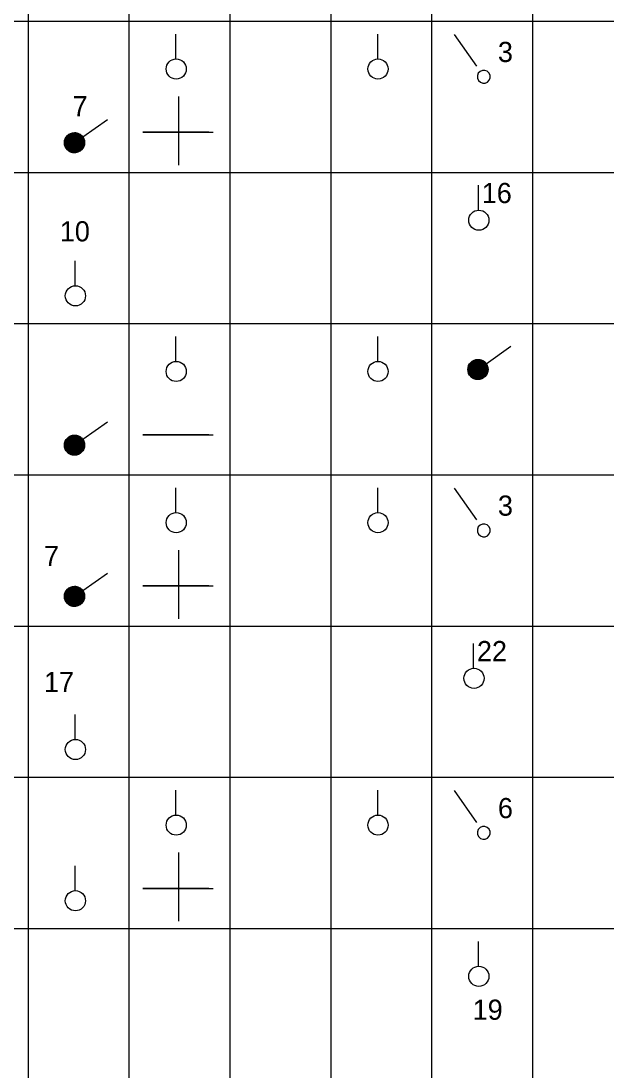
# Model space of a CAD drawing. Extents: x -28 to 822, y 61 to 665.
# Drawn here: x 399.9 to 458, y 142.6 to 246.8 of the extents above; entities that cross this region are included whole.
import ezdxf

# ---------------------------------------------------------------- set-up
doc = ezdxf.new("R2010")
doc.units = 0

# ---------------------------------------------------------------- blocks, each defined once
blk = doc.blocks.new('_X10')
for p, q in [((370.45, 480.11), (371.52, 481.17)), ((370.45, 480.13), (371.5, 481.17)), ((370.45, 480.14), (371.48, 481.17)), ((370.45, 480.16), (371.46, 481.17)), ((370.45, 480.18), (371.45, 481.17)), ((370.45, 480.2), (371.43, 481.17)), ((370.45, 480.21), (371.41, 481.17)), ((370.45, 480.23), (371.39, 481.17)), ((370.46, 480.06), (371.56, 481.17)), ((370.46, 480.08), (371.55, 481.17)), ((370.46, 480.09), (371.53, 481.17)), ((370.46, 480.25), (371.37, 481.17)), ((370.46, 480.27), (371.35, 481.17)), ((370.46, 480.29), (371.33, 481.17)), ((370.46, 480.01), (371.61, 481.16)), ((370.46, 480.03), (371.6, 481.16)), ((370.46, 480.04), (371.58, 481.16)), ((370.46, 480.31), (371.31, 481.16)), ((370.46, 480.33), (371.29, 481.16)), ((370.47, 480), (371.63, 481.16)), ((370.47, 480.35), (371.27, 481.16)), ((370.47, 479.97), (371.66, 481.15)), ((370.47, 479.98), (371.64, 481.15)), ((370.47, 480.37), (371.25, 481.15)), ((370.48, 479.95), (371.67, 481.15)), ((370.48, 480.4), (371.23, 481.15)), ((370.48, 479.93), (371.7, 481.14)), ((370.48, 479.94), (371.68, 481.14)), ((370.48, 480.42), (371.2, 481.14)), ((370.49, 479.91), (371.71, 481.14)), ((370.49, 479.88), (371.74, 481.13)), ((370.49, 479.9), (371.73, 481.13)), ((370.49, 480.45), (371.18, 481.13)), ((370.5, 479.87), (371.75, 481.13)), ((370.5, 480.47), (371.15, 481.13)), ((370.5, 479.86), (371.77, 481.12)), ((370.51, 479.84), (371.78, 481.12)), ((370.51, 480.5), (371.13, 481.12)), ((370.51, 479.83), (371.79, 481.11)), ((370.52, 479.82), (371.81, 481.11)), ((370.52, 480.52), (371.1, 481.11)), ((370.52, 479.81), (371.82, 481.1)), ((370.53, 479.79), (371.83, 481.1)), ((370.53, 480.55), (371.07, 481.1)), ((370.53, 479.78), (371.84, 481.09)), ((370.54, 479.77), (371.86, 481.09)), ((370.54, 479.76), (371.87, 481.08)), ((370.54, 480.58), (371.04, 481.08)), ((370.55, 479.74), (371.88, 481.08)), ((370.55, 479.73), (371.89, 481.07)), ((370.56, 480.62), (371.01, 481.07)), ((370.56, 479.72), (371.9, 481.06)), ((370.57, 479.71), (371.92, 481.06)), ((370.57, 479.7), (371.93, 481.05)), ((370.58, 479.69), (371.94, 481.05)), ((370.58, 480.66), (370.97, 481.05)), ((370.59, 479.67), (371.95, 481.04)), ((370.59, 479.66), (371.96, 481.03)), ((370.6, 479.65), (371.97, 481.03)), ((370.6, 479.64), (371.98, 481.02)), ((370.6, 480.7), (370.93, 481.02)), ((370.61, 479.63), (371.99, 481.01)), ((370.62, 479.62), (372, 481.01)), ((370.63, 479.61), (372.02, 481)), ((370.63, 479.6), (372.03, 480.99)), ((370.64, 480.75), (370.87, 480.99)), ((370.64, 479.59), (372.04, 480.98)), ((370.65, 479.58), (372.05, 480.98)), ((370.66, 479.57), (372.06, 480.97)), ((370.66, 479.56), (372.07, 480.96)), ((370.67, 479.55), (372.08, 480.95)), ((370.68, 479.54), (372.09, 480.95)), ((370.69, 479.53), (372.1, 480.94)), ((370.7, 479.52), (372.11, 480.93)), ((370.7, 479.51), (372.11, 480.92)), ((370.71, 480.84), (370.79, 480.92)), ((370.71, 479.5), (372.12, 480.91)), ((370.72, 479.49), (372.13, 480.9)), ((370.73, 479.48), (372.14, 480.9)), ((370.74, 479.47), (372.15, 480.89)), ((370.75, 479.46), (372.16, 480.88)), ((370.76, 479.46), (372.17, 480.87)), ((370.76, 479.45), (372.18, 480.86)), ((370.77, 479.44), (372.19, 480.85)), ((370.78, 479.43), (372.19, 480.84)), ((370.79, 479.42), (372.2, 480.83)), ((370.8, 479.41), (372.21, 480.82)), ((370.81, 479.4), (372.22, 480.81)), ((370.82, 479.4), (372.23, 480.8)), ((370.83, 479.39), (372.24, 480.79)), ((370.84, 479.38), (372.24, 480.78)), ((370.85, 479.37), (372.25, 480.77)), ((370.86, 479.37), (372.26, 480.76)), ((370.87, 479.36), (372.27, 480.75)), ((370.88, 479.35), (372.27, 480.74)), ((370.89, 479.34), (372.28, 480.73)), ((370.9, 479.34), (372.29, 480.72)), ((370.91, 479.33), (372.29, 480.71)), ((370.92, 479.32), (372.3, 480.7)), ((370.93, 479.32), (372.31, 480.69)), ((370.95, 479.31), (372.31, 480.68)), ((370.96, 479.3), (372.32, 480.67)), ((370.97, 479.3), (372.33, 480.66)), ((370.98, 479.29), (372.33, 480.64)), ((370.99, 479.28), (372.34, 480.63)), ((371, 479.28), (372.35, 480.62)), ((371.01, 479.27), (372.35, 480.61)), ((371.03, 479.27), (372.36, 480.6)), ((371.04, 479.26), (372.36, 480.59)), ((371.05, 479.26), (372.37, 480.57)), ((371.06, 479.25), (372.37, 480.56)), ((371.08, 479.25), (372.38, 480.55)), ((371.09, 479.24), (372.38, 480.54)), ((371.1, 479.24), (372.39, 480.52)), ((371.11, 479.23), (372.39, 480.51)), ((371.13, 479.23), (372.4, 480.5)), ((371.14, 479.22), (372.4, 480.48)), ((371.15, 479.22), (372.41, 480.47)), ((371.17, 479.21), (372.41, 480.46)), ((371.18, 479.21), (372.41, 480.44)), ((371.2, 479.21), (372.42, 480.43)), ((371.21, 479.2), (372.42, 480.42)), ((371.22, 479.2), (372.43, 480.4)), ((371.24, 479.2), (372.43, 480.39)), ((371.25, 479.19), (372.43, 480.37)), ((371.27, 479.19), (372.43, 480.36)), ((371.28, 479.19), (372.44, 480.34)), ((371.3, 479.18), (372.44, 480.33)), ((371.31, 479.18), (372.44, 480.31)), ((371.33, 479.18), (372.44, 480.3)), ((371.34, 479.18), (372.45, 480.28)), ((371.36, 479.18), (372.45, 480.26)), ((371.38, 479.17), (372.45, 480.25)), ((371.39, 479.17), (372.45, 480.23)), ((371.41, 479.17), (372.45, 480.21)), ((371.43, 479.17), (372.45, 480.2)), ((371.44, 479.17), (372.45, 480.18)), ((371.46, 479.17), (372.45, 480.16)), ((371.48, 479.17), (372.45, 480.14)), ((371.5, 479.17), (372.45, 480.13)), ((371.52, 479.17), (372.45, 480.11)), ((371.54, 479.18), (372.45, 480.09)), ((371.56, 479.18), (372.45, 480.07)), ((371.58, 479.18), (372.44, 480.05)), ((371.6, 479.18), (372.44, 480.03)), ((371.62, 479.19), (372.44, 480.01)), ((371.64, 479.19), (372.43, 479.99)), ((371.66, 479.19), (372.43, 479.96)), ((371.68, 479.2), (372.42, 479.94)), ((371.71, 479.21), (372.42, 479.92)), ((371.73, 479.21), (372.41, 479.89)), ((371.76, 479.22), (372.4, 479.87)), ((371.78, 479.23), (372.4, 479.84)), ((371.81, 479.24), (372.39, 479.81)), ((371.84, 479.25), (372.37, 479.78)), ((371.87, 479.27), (372.36, 479.75)), ((371.91, 479.28), (372.34, 479.72)), ((371.95, 479.3), (372.32, 479.68)), ((371.99, 479.33), (372.29, 479.63)), ((372.05, 479.37), (372.26, 479.58))]:
    blk.add_line(p, q)

msp = doc.modelspace()

# ---------------------------------------------------------------- linework, layer by layer
for p, q in [((400.62, 381.74), (400.62, 111.74)), ((410.62, 381.74), (410.62, 111.74)), ((410.62, 381.74), (410.62, 111.74)), ((420.62, 381.74), (420.62, 111.74)), ((430.62, 381.74), (430.62, 111.74)), ((440.62, 381.74), (440.62, 111.74)), ((450.62, 381.74), (450.62, 111.74)), ((5.07, 246.74), (540.62, 246.74)), ((5.07, 246.74), (540.62, 246.74)), ((415.28, 242.94), (415.28, 245.47)), ((435.28, 242.94), (435.28, 245.47)), ((442.87, 245.42), (445.07, 242.27)), ((415.54, 239.27), (415.54, 232.47)), ((406.04, 235.27), (408.49, 237)), ((339.09, 231.74), (540.62, 231.74)), ((445.28, 227.94), (445.28, 230.47)), ((405.28, 220.44), (405.28, 222.97)), ((5.07, 216.74), (540.62, 216.74)), ((415.28, 212.94), (415.28, 215.47)), ((435.28, 212.94), (435.28, 215.47)), ((446.04, 212.77), (448.49, 214.5)), ((406.04, 205.27), (408.49, 207)), ((5.07, 201.74), (540.62, 201.74)), ((5.07, 201.74), (540.62, 201.74)), ((5.07, 201.74), (540.62, 201.74)), ((54.09, 201.74), (540.62, 201.74)), ((415.28, 197.94), (415.28, 200.47)), ((435.28, 197.94), (435.28, 200.47)), ((442.87, 200.42), (445.07, 197.27)), ((415.54, 194.27), (415.54, 187.47)), ((406.04, 190.27), (408.49, 192)), ((348.12, 186.74), (540.62, 186.74)), ((444.79, 182.5), (444.79, 185.03)), ((405.28, 175.44), (405.28, 177.97)), ((5.07, 171.74), (540.62, 171.74)), ((415.28, 167.94), (415.28, 170.47)), ((435.28, 167.94), (435.28, 170.47)), ((442.87, 170.42), (445.07, 167.27)), ((415.54, 164.27), (415.54, 157.47)), ((405.28, 160.44), (405.28, 162.97)), ((348.12, 156.74), (540.62, 156.74)), ((445.28, 152.94), (445.28, 155.47))]:
    msp.add_line(p, q)
for points in [[(412.94, 235.72), (418.54, 235.72), (412, 235.72), (418.96, 235.72)], [(412.94, 205.72), (418.54, 205.72), (412, 205.72), (418.96, 205.72)], [(412.94, 190.72), (418.54, 190.72), (412, 190.72), (418.96, 190.72)], [(412.94, 160.72), (418.54, 160.72), (412, 160.72), (418.96, 160.72)]]:
    msp.add_lwpolyline(points)
for centre in [(415.31, 242), (435.31, 242), (405.22, 234.69), (445.31, 227), (405.31, 219.5), (415.31, 212), (435.31, 212), (445.22, 212.19), (405.22, 204.69), (415.31, 197), (435.31, 197), (405.22, 189.69), (444.83, 181.56), (405.31, 174.5), (415.31, 167), (435.31, 167), (405.31, 159.5), (445.31, 152)]:
    msp.add_circle(centre, 1)
for centre, start, end in [((445.8, 241.23), 35, 215), ((445.8, 241.23), 215, 35), ((445.8, 196.23), 35, 215), ((445.8, 196.23), 215, 35), ((445.8, 166.23), 35, 215), ((445.8, 166.23), 215, 35)]:
    msp.add_arc(centre, 0.64, start, end)

# ---------------------------------------------------------------- block references
at = {"rotation": -92.29148628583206}
for p in [(-59.72, 625.04), (-19.72, 602.54), (-59.72, 595.04), (-59.72, 580.04)]:
    msp.add_blockref('_X10', p, dxfattribs=at)

# ---------------------------------------------------------------- texts
for s, p in [('3', (447.2, 242.69)), ('7', (405.03, 237.31)), ('16', (445.6, 228.7)), ('10', (403.77, 224.9)), ('3', (447.2, 197.69)), ('7', (402.2, 192.69)), ('22', (445.12, 183.26)), ('17', (402.2, 180.19)), ('6', (447.2, 167.69)), ('19', (444.7, 147.69))]:
    msp.add_text(s, height=2).set_placement(p)

doc.saveas('drawing.dxf')
